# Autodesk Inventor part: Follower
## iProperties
Created: 2006-07
Part Number: Follower
Document SubType Name: Modeling
Designer: Maxime Debono
Material: Stainless Steel, 440C
Mass: 85.9708 g
Surface Area: 48.9346 cm^2
Volume: 11.093 cm^3
Density: 7.75 g/cm^3
Author: Maxime Debono
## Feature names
1. Extrusion1
2. Extrusion2
3. Extrusion3
4. Fillet1
5. Extrusion4
